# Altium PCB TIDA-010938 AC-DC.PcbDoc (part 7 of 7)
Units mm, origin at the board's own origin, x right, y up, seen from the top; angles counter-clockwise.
Board outline 275 x 170 mm, 4 copper layers (Top Layer, Layer 1, Layer 2, Bottom Layer), stack 1.787 mm thick; 711 components, 426 nets, 2196 pads, 1444 vias.
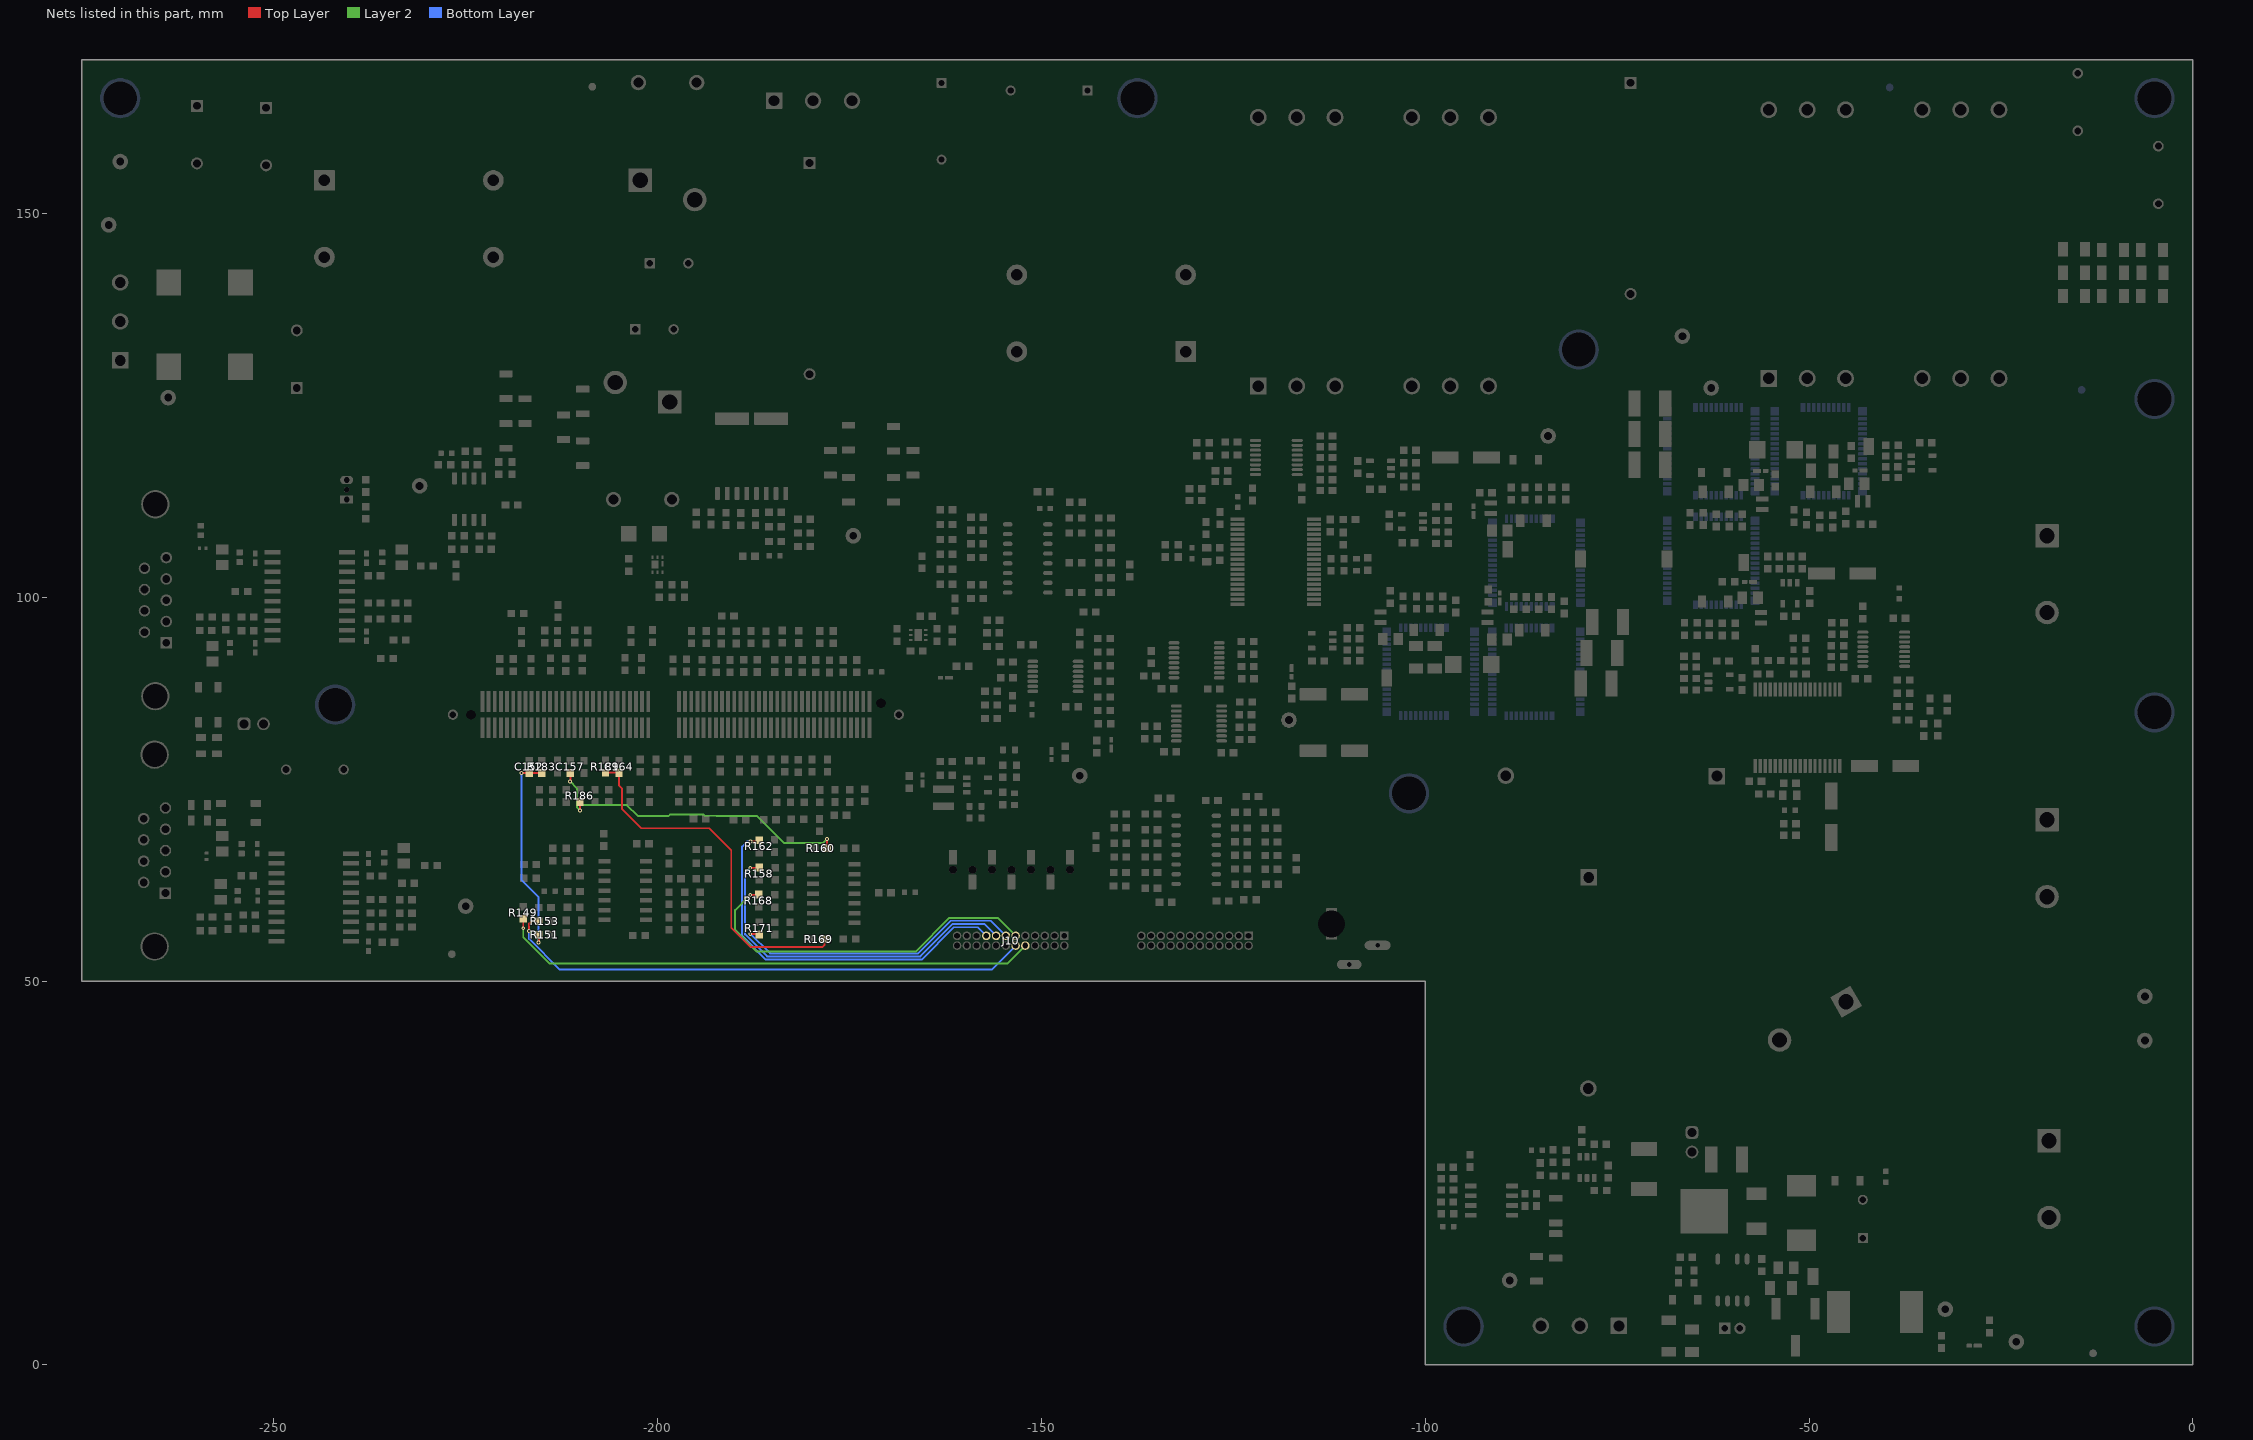
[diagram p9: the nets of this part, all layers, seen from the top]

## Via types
v1: diameter 0.508, hole 0.254, Top Layer to Bottom Layer, tented both sides, 1436 vias
v2: diameter 0.508, hole 0.254, Top Layer to Bottom Layer, 6 vias
v3: diameter 0.5, hole 0.2, Top Layer to Bottom Layer, 2 vias

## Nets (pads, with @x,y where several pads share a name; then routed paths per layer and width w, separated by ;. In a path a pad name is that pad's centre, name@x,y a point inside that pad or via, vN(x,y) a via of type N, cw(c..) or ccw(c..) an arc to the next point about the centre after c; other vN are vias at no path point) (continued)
VS_Batt1: C152.2 R151.2 R183.2 | length 26.6
  Top Layer w0.25: v1(-217.75,77.1) C152.2@-216.725,77.1 R183.2@-215.075,77.1 ; v1@-215.475,55.05 -215.473,55.052 R151.2@-215.473,56.02
  Bottom Layer w0.25: v1(-217.75,77.1) -217.75,63.177 -215.5,60.927 v1@-215.5,55.05
  other v1: -215.5,55
VS_Batt1+: J10.10 R149.2 | length 70.1
  Top Layer w0.25: R149.2@-217.5,58.094 -217.5,56.975 v1@-217.475,56.95
  Layer 2 w0.25: v1@-217.5,56.85 -217.494,56.844 -217.494,55.694 -214.1,52.3 -154.415,52.3 J10.10@-152.095,54.62
  other v1: -217.5,56.875
VS_Batt1-: J10.12 R153.2 | length 69.7
  Top Layer w0.25: v1(-216.725,56.5) -216.725,57.475 -216.402,57.798 R153.2@-215.473,57.798
  Bottom Layer w0.25: v1@-216.8,56.5 -216.725,56.425 -216.725,55.477 -212.748,51.5 -156.485,51.5 J10.12@-153.365,54.62
VS_Boost1: C157.2 R160.2 R186.1 | length 42.4
  Top Layer w0.25: v1@-211.363,76.137 C157.2@-211.363,77.101 ; v1(-210.119,72.194) R186.1@-210.119,73.328 ; R160.2@-177.975,67.475 -177.95,67.5 v1(-177.95,68.475)
  Layer 2 w0.25: v1(-211.4,76) -210.5,75.1 -210.5,72.922 ; v1(-210.119,72.194) -210.119,72.263 -210.5,72.645 -210.5,72.922 ; v1(-177.95,68.475) -178.425,68 -183.552,68 -187.052,71.5 -192.352,71.5 -192.381,71.529 -193.852,71.529 -194.002,71.679 -198.369,71.679 -198.548,71.5 -202.573,71.5 -203.996,72.922 -210.5,72.922
VS_Boost1+: J10.15 R158.2 | length 46.4
  Top Layer w0.25: v1(-187.925,64.75) -186.8,64.75 R158.2@-186.775,64.725
  Bottom Layer w0.25: v1@-187.95,64.725 -188.6,64.075 -188.6,56.077 -185.723,53.2 -165.775,53.2 -161.525,57.45 -157.465,57.45 J10.15@-155.905,55.89
VS_Boost1-: J10.17 R162.2 | length 49.5
  Top Layer w0.25: v1(-187.9,68.2) -186.7,68.2 R162.2@-186.675,68.225
  Bottom Layer w0.25: v1(-187.9,68.2) -188.297,68.2 -189,67.497 -189,55.911 -185.889,52.8 -165.609,52.8 -161.409,57 -158.285,57 J10.17@-157.175,55.89
VS_Boost2: C164.2 R169.2 R189.1 | length 47.2
  Top Layer w0.25: R189.1@-206.791,77.139 C164.2@-205.014,77.139 ; C164.2@-205.013,77.101 -205.013,75.436 -204.625,75.048 -204.625,72.375 -202.15,69.9 -193.275,69.9 -190.4,67.025 -190.4,56.95 -187.9,54.45 -178.5,54.45 -178.232,54.718 R169.2@-178.232,55.472
VS_Boost2+: J10.11 R168.2 | length 46.8
  Top Layer w0.25: v1(-187.925,61.225) R168.2@-186.825,61.225
  Layer 2 w0.25: v1@-188.05,61.1 -189.9,59.25 -189.9,56.65 -187.071,53.821 -166.379,53.821 -161.975,58.225 -155.7,58.225 J10.11@-153.365,55.89
VS_Boost2-: J10.13 R171.2 | length 38
  Top Layer w0.25: v1(-187.925,56.15) -186.95,56.15 R171.2@-186.925,56.125
  Bottom Layer w0.25: v1@-188,56.25 -185.35,53.6 -166.075,53.6 -161.825,57.85 -156.595,57.85 J10.13@-154.635,55.89
pads on no net: FID1.1 FID2.1 FID3.1 FID4.1 FID5.1 FID6.1 J2.2 J8. J8.6 J10.18 J10.19 J10.20 J10.21 J11.1 J11.2 J11.3 J11.4 J11.5 J11.6 J11.8 J11.9 J11.11 J11.15 J11.17 J11.20 J11.27 J11.32 J11.34 J11.36 J11.37 J11.41 J11.42 J11.43 J11.44 J11.45 J11.58 J11.60 J11.62 J11.64 J11.66 J11.71 J11.73 J11.85 J11.110 J11.113 J11.114 J11.115 J11.116 J11.117 J11.118 J11.119 J11.120 J11.181 J11.182 J11.185 J11.186 J12.18 J12.20 J12.22 J15.1 J15.8 J17.3 J17.4 J17.6 J17.7 J17.8 J17.9 L1.2 L1.3 L1.4 L1.5 L1.7 L1.8 L1.9 L1.10 L1.11 L1.12 L4.2 L4.3 L4.4 L4.5 L4.7 L4.8 L4.9 L4.10 L4.11 L4.12 LBL1.0 MP1. MP2. MP3. MP3.1 MP5. MP5.1 MP6. MP6.1 MP7. MP7.1 MP8. MP8.1 MP9. MP10. MP10.1 MP12. MP12.1 R6. R99.1 R125.2 R132.3 U2.1 U2.16 U2.17 U2.27 U2.43 U2.47 U2.52 U3.32 U4.1 U4.16 U4.17 U4.27 U4.43 U4.47 U4.52 U8.1 U8.16 U8.17 U8.27 U8.43 U8.47 U8.52 U9.1 U9.16 U9.17 U9.27 U9.43 U9.47 U9.52 U10.32 U11.1 U11.16 U11.17 U11.27 U11.43 U11.47 U11.52 U15.1 U15.16 U15.17 U15.27 U15.43 U15.47 U15.52 U16.10 U19.2 U19.5 U19.7@-166.06,94.626 U19.7@-166.06,95.526 U23.6 U24.6 U30.7

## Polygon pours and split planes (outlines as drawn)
"DC Bus-" on Bottom Layer "Bottom Layer-DC Bus- 1" (solid, remove dead copper, pour order 124): 59 vertices, not listed, extent -241.6,15 -26.5,123.5
SW_1 on Bottom Layer "BOTTOM_LAYER_SW_1_P025" (solid, remove dead copper, pour order 25): 31 vertices, not listed, extent -96.3,82.85 -82.75,130.125
12V_HVN on Bottom Layer "BOTTOM_LAYER_12V_HVN_P182" (solid, remove dead copper, pour order 182): -42,25 -42.25,25.25 -42.25,27.5 -42,27.75 -40,27.75 -39.5,27.25 -39.5,25
PE on Bottom Layer "BOTTOM_LAYER_PE_P154" (solid, remove dead copper, pour order 154): -272,137.25 -272,134.5 -259,134.5 -259,148 -265,154 -265,161 -264,162 -249,162 -249,167 -265,167 -267,169 -274,169 -274,156 -265,147 -265,137.25
NetF2_1 on Bottom Layer "BOTTOM_LAYER_NETF2_1_P150" (solid, remove dead copper, pour order 150): 22 vertices, not listed, extent -256,124 -241,159
VAC_N on Bottom Layer "BOTTOM_LAYER_VAC_N_P142" (solid, remove dead copper, pour order 142): -206,150 -204,148 -204,143 -202,141 -200,141 -199,142 -199,157 -201,159 -222,159 -224,157 -224,152 -222,150
PE2 on Bottom Layer "BOTTOM_LAYER_PE2_P140" (solid, remove dead copper, pour order 140): -143,161 -146.25,164.25 -146.25,166.75 -143.5,169.5 -143.353,169.353 -134.603,169.353 -131.5,166.25 -131.5,159.25 -141.25,159.25
ACLOAD_N on Bottom Layer "BOTTOM_LAYER_ACLOAD_N_P137" (solid, remove dead copper, pour order 137): 20 vertices, not listed, extent -198,138 -150,169
PE3 on Bottom Layer "BOTTOM_LAYER_PE3_P135" (solid, remove dead copper, pour order 135): -17,169 -17,167 -11,167 -11,163 -9,161 -6,161 -6,158 -3,158 -3,161 -1,161 -1,168.884 -0.934,168.95 -0.983,169
NetC103_2 on Bottom Layer "BOTTOM_LAYER_NETC103_2_P134" (solid, remove dead copper, pour order 134): 33 vertices, not listed, extent -135,125.25 -1,167
"DC Bus+" on Bottom Layer "BOTTOM_LAYER_DC_BUS+_P120" (solid, remove dead copper, pour order 120): -27,14 -27,54 -24,57 -24,111.75 -22,113.75 -11,113.75 -11,14
NetC229_1 on Bottom Layer "BOTTOM_LAYER_NETC229_1_P109" (solid, remove dead copper, pour order 109): -66.5,16 -67,16.5 -67,26 -65.5,27.5 -60.5,27.5 -60.5,16
"DC Bus+" on Bottom Layer "BOTTOM_LAYER_DC_BUS+_P096" (solid, remove dead copper, pour order 96): 19 vertices, not listed, extent -87.5,1.5 -69.5,39.5
"DC Bus-" on Bottom Layer "BOTTOM_LAYER_DC_BUS-_P086" (solid, remove dead copper, pour order 86): -102.75,83 -94.75,75 -94.75,69 -88.25,62.5 -80.75,62.5 -69,62.5 -60.75,70.75 -60.75,82.25 -62.5,84 -70.5,84 -82.5,72 -90.25,72 -92.5,74.25 -92.5,78.5 -97,83
"DC Bus-" on Bottom Layer "BOTTOM_LAYER_DC_BUS-_P082" (solid, remove dead copper, pour order 82): 19 vertices, not listed, extent -107,81.75 -96.75,95.25
SW_mid on Bottom Layer "BOTTOM_LAYER_SW_MID_P059" (solid, remove dead copper, pour order 59): 18 vertices, not listed, extent -81.25,100 -67,109.5
"DC Bus-" on Bottom Layer "Bottom Layer-DC Bus-" (solid, remove dead copper, pour order 72): 29 vertices, not listed, extent -79.5,109.5 -39.5,136
"DC Bus+" on Bottom Layer "BOTTOM_LAYER_DC_BUS+_P066" (solid, remove dead copper, pour order 66): -69,114.5 -69.95,115.45 -69.95,126.95 -69.4,127.5 -66,127.5 -66,126.5 -67,125.5 -67,122.5 -66.268,121.768 -66.268,116.732 -67.095,115.905 -67.095,114.5
"DC Bus+" on Bottom Layer "BOTTOM_LAYER_DC_BUS+_P007" (solid, remove dead copper, pour order 7): -82,95 -80.5,96.5 -78,96.5 -78,95 -78,79.75 -83.5,74.25 -89.35,74.25 -90.75,75.65 -90.75,78.05 -87.8,81 -83.75,81 -82,82.75
SW_2 on Bottom Layer "BOTTOM_LAYER_SW_2_P000" (solid, remove dead copper, pour order 0): 27 vertices, not listed, extent -65.25,97.4 -53,130
"DC Bus-" on Layer 1 "Layer 1-DC Bus-" (solid, remove dead copper, pour order 114): 47 vertices, not listed, extent -241.6,15 -75.5,123.5
GND_ISO_COMM on Layer 1 "LAYER_1_GND_ISO_COMM_P171" (solid, remove dead copper, pour order 171): -274.7,116.5 -272.4,118.8 -253.3,118.8 -248.6,114.1 -248.6,50.7 -273.3,50.7 -274.7,52.1
SW_2 on Layer 1 "LAYER_1_SW_2_P075" (solid, remove dead copper, pour order 75): 32 vertices, not listed, extent -67,87 -42,116.6
SW_1 on Layer 1 "Layer 1-SW_1" (solid, remove dead copper, pour order 57): 30 vertices, not listed, extent -117,93.5 -81.7,122
"DC Bus+" on Layer 1 "Layer 1-DC Bus+" (solid, remove dead copper, pour order 198): 63 vertices, not listed, extent -91.5,2 -2,130
VAC_SW+ on Layer 1 "LAYER_1_VAC_SW+_P194" (solid, remove dead copper, pour order 194): -182,127 -182,132 -179,135 -150,135 -148,133 -148,127
ACLOAD_N on Layer 1 "LAYER_1_ACLOAD_N_P193" (solid, remove dead copper, pour order 193): -151,140 -151,149 -165,149 -172,156 -182,156 -182,140
ACLOAD_N on Layer 1 "LAYER_1_ACLOAD_N_P192" (solid, remove dead copper, pour order 192): -197,150 -178,150 -172,156 -172,167 -176,167 -176,159 -177,158 -197,158 -197,149
PE on Layer 1 "LAYER_1_PE_P155" (solid, remove dead copper, pour order 155): -272,137.25 -272,134.5 -259,134.5 -259,148 -265,154 -265,161 -264,162 -249,162 -249,167 -265,167 -267,169 -274,169 -274,156 -265,147 -265,137.25
NetF2_1 on Layer 1 "LAYER_1_NETF2_1_P151" (solid, remove dead copper, pour order 151): 22 vertices, not listed, extent -256,124 -241,159
VAC_N on Layer 1 "LAYER_1_VAC_N_P145" (solid, remove dead copper, pour order 145): -224,152 -212,152 -210,150 -206,150 -204,148 -204,143 -202,141 -200,141 -199,142 -199,157 -201,159 -222,159 -224,157
VAC_L on Layer 1 "LAYER_1_VAC_L_P144" (solid, remove dead copper, pour order 144): -206.75,125.75 -210.25,129.25 -210.25,136 -215.25,141 -223,141 -225,143 -225,146 -223.5,147.5 -213.5,147.5 -202,136 -202,126.5 -202.75,125.75
NetC103_2 on Layer 1 "LAYER_1_NETC103_2_P132" (solid, remove dead copper, pour order 132): 31 vertices, not listed, extent -135,125.25 -1,167
NetC116_2 on Layer 1 "LAYER_1_NETC116_2_P106" (solid, remove dead copper, pour order 106): 24 vertices, not listed, extent -68.5,4 -44.5,20
"DC Bus-" on Layer 1 "LAYER_1_DC_BUS-_P092" (solid, remove dead copper, pour order 92): 23 vertices, not listed, extent -69.5,-1.25 -21.75,28.5
"DC Bus-" on Layer 1 "Layer 1-DC Bus- 1" (solid, remove dead copper, pour order 91): 34 vertices, not listed, extent -59,65.5 -28,121.5
"DC Bus-" on Top Layer "TOP_LAYER_DC_BUS-_P203" (solid, remove dead copper, pour order 203): 35 vertices, not listed, extent -242,16 -77.133,123
3V3_HVN on Top Layer "TOP_LAYER_3V3_HVN_P180" (solid, remove dead copper, pour order 180): 47 vertices, not listed, extent -125.525,50.5 -98.25,94
NetC103_1 on Top Layer "Top Layer-NetC103_1" (solid, remove dead copper, pour order 202): 30 vertices, not listed, extent -135,126.25 -10,169
"DC Bus-" on Top Layer "Top Layer-DC Bus-" (solid, remove dead copper, pour order 201): 63 vertices, not listed, extent -91.5,11.5 -2,127.038
SW_1 on Top Layer "TOP_LAYER_SW_1_P200" (solid, remove dead copper, pour order 200): -98,115 -99,116 -100,117 -100,121 -96,121 -95,120 -95,115
SW_2 on Top Layer "TOP_LAYER_SW_2_P199" (solid, remove dead copper, pour order 199): -45,105 -45,100 -41,100 -41,105
ACLOAD_N on Top Layer "TOP_LAYER_ACLOAD_N_P190" (solid, remove dead copper, pour order 190): -156,169 -151,169 -151,142 -153,140 -156,140
VAC_N on Top Layer "TOP_LAYER_VAC_N_P189" (solid, remove dead copper, pour order 189): -224,158 -224,152 -201,152 -200,153 -200,158
NetF2_1 on Top Layer "TOP_LAYER_NETF2_1_P188" (solid, remove dead copper, pour order 188): -253,158 -253,151 -241,151 -241,158
PE3 on Top Layer "TOP_LAYER_PE3_P187" (solid, remove dead copper, pour order 187): -17,168.75 -17,167 -11,167 -11,163 -9,161 -6,161 -6,158 -3,158 -3,161 -1,161 -0.983,161.017 -0.983,169 -16.75,169
PE2 on Top Layer "TOP_LAYER_PE2_P186" (solid, remove dead copper, pour order 186): -146.25,166.75 -143.647,169.353 -134.603,169.353 -131.5,166.25 -131.5,159.25 -141.25,159.25 -146.25,164.25
PE on Top Layer "TOP_LAYER_PE_P185" (solid, remove dead copper, pour order 185): -274,160 -265,160 -265,161 -264,162 -249,162 -249,167 -265,167 -267,169 -274,169
12V_HVN on Top Layer "TOP_LAYER_12V_HVN_P183" (solid, remove dead copper, pour order 183): -42.5,25.25 -39.25,25.25 -39.25,28 -42.5,28
SW_1 on Top Layer "TOP_LAYER_SW_1_P181" (solid, remove dead copper, pour order 181): -86.75,93.75 -84,93.75 -83.5,94.25 -83.5,96.5 -83.65,96.65 -84.9,96.65 -85.75,95.8 -86.75,95.8
SW_1 on Top Layer "TOP_LAYER_SW_1_P179" (solid, remove dead copper, pour order 179): -117.5,121.75 -117.5,120.295 -115.955,120.295 -115.25,121 -115.25,121.5 -115.5,121.75
12V_HVN on Top Layer "TOP_LAYER_12V_HVN_P178" (solid, remove dead copper, pour order 178): -111.25,89.75 -107.5,89.75 -107.5,79 -107.75,78.75 -111,78.75 -111.25,79
"DC Bus-" on Top Layer "TOP_LAYER_DC_BUS-_P177" (solid, remove dead copper, pour order 177): -125.5,109.5 -125.5,111.5 -123,111.5 -123,109.5
"DC Bus-" on Top Layer "TOP_LAYER_DC_BUS-_P176" (solid, remove dead copper, pour order 176): -123.5,98.5 -127.5,98.5 -127.5,102.5 -126.5,103.5 -126.5,105.05 -126.05,105.05 -126.05,105.625 -123.625,105.625 -123.5,105.5
SW_1 on Top Layer "TOP_LAYER_SW_1_P174" (solid, remove dead copper, pour order 174): -85.725,114.075 -85.75,114.1 -85.75,119 -84.5,119 -81.7,116.2 -81.7,114.075
"DC Bus-" on Top Layer "TOP_LAYER_DC_BUS-_P173" (solid, remove dead copper, pour order 173): -184.25,106.25 -184.25,111.5 -181.75,111.5 -181.446,111.196 -181.446,109.377 -181.76,109.064 -181.794,109.098 -182.446,109.098 -182.446,106.354 -182.55,106.25
"DC Bus-" on Top Layer "TOP_LAYER_DC_BUS-_P172" (solid, remove dead copper, pour order 172): -117,78.75 -116.5,78.25 -113,78.25 -112.25,79 -112.25,89.25 -112.5,89.5 -115.75,89.5 -116.5,88.75 -116.5,85.75 -116.75,85.5 -118.25,85.5 -119,84.75 -119,78.75
"DC Bus-" on Top Layer "TOP_LAYER_DC_BUS-_P170" (solid, remove dead copper, pour order 170): -107,85.75 -103,85.75 -103,93.55 -107,93.55
"DC Bus-" on Top Layer "TOP_LAYER_DC_BUS-_P169" (solid, remove dead copper, pour order 169): -43.399,118.351 -41.25,118.351 -41.25,120.849 -43.397,120.849 -43.399,120.851
SW_mid on Top Layer "TOP_LAYER_SW_MID_P168" (solid, remove dead copper, pour order 168): -69.5,103.75 -67,103.75 -67,106.25 -67.002,106.248 -69.498,106.248 -69.5,106.25
SW_mid on Top Layer "TOP_LAYER_SW_MID_P166" (solid, remove dead copper, pour order 166): -81.25,103.25 -78.75,103.25 -78.75,106.75 -81.25,106.75
NetR112_2 on Top Layer "TOP_LAYER_NETR112_2_P165" (solid, remove dead copper, pour order 165): -213.5,121.4 -213.5,119.65 -208.25,119.65 -208.25,121.4
NetR111_2 on Top Layer "TOP_LAYER_NETR111_2_P164" (solid, remove dead copper, pour order 164): -213.5,124.65 -213.5,122.9 -208.25,122.9 -208.25,124.65
NetR123_2 on Top Layer "TOP_LAYER_NETR123_2_P163" (solid, remove dead copper, pour order 163): -221,123.65 -221,121.9 -215.75,121.9 -215.75,123.65
NetR122_2 on Top Layer "TOP_LAYER_NETR122_2_P162" (solid, remove dead copper, pour order 162): -221,126.9 -221,125.15 -215.75,125.15 -215.75,126.9
NetC81_1 on Top Layer "TOP_LAYER_NETC81_1_P161" (solid, remove dead copper, pour order 161): -172.25,113.269 -172.25,111 -168.167,111 -168.167,113.269
NetC45_1 on Top Layer "TOP_LAYER_NETC45_1_P160" (solid, remove dead copper, pour order 160): -178.25,113.275 -178.25,111 -174,111 -174,113.275
NetR128_2 on Top Layer "TOP_LAYER_NETR128_2_P159" (solid, remove dead copper, pour order 159): -171.025,116.75 -171.025,115 -165.775,115 -165.775,116.75
NetR117_2 on Top Layer "TOP_LAYER_NETR117_2_P158" (solid, remove dead copper, pour order 158): -179.25,116.55 -179.25,114.8 -174,114.8 -174,116.55
NetR127_2 on Top Layer "TOP_LAYER_NETR127_2_P157" (solid, remove dead copper, pour order 157): -170.75,120 -170.75,118.5 -163.5,118.5 -163.5,120
NetR116_2 on Top Layer "TOP_LAYER_NETR116_2_P156" (solid, remove dead copper, pour order 156): -179.25,120.25 -179.25,118.5 -174,118.5 -174,120.25
AC_L on Top Layer "TOP_LAYER_AC_L_P148" (solid, remove dead copper, pour order 148): -273,140 -265,140 -265,138 -262,138 -262,146 -273,146
NetF1_1 on Top Layer "TOP_LAYER_NETF1_1_P149" (solid, remove dead copper, pour order 149): -256,146 -261,151 -263,153 -263,158 -257,158 -257,151 -255,149 -241,149 -241,134 -250,134 -250,137 -254,137 -256,139
AC_N on Top Layer "TOP_LAYER_AC_N_P147" (solid, remove dead copper, pour order 147): -273,132 -262,132 -262,125 -263,124 -273,124
NetF2_1 on Top Layer "TOP_LAYER_NETF2_1_P146" (solid, remove dead copper, pour order 146): -256,131.65 -250.65,131.65 -248,129 -245,129 -244,128 -244,125 -245,124 -252,124 -256,128
VAC_L on Top Layer "TOP_LAYER_VAC_L_P141" (solid, remove dead copper, pour order 141): -206.75,125.75 -210.25,129.25 -210.25,136 -215.25,141 -223,141 -225,143 -225,146 -223.5,147.5 -213.5,147.5 -202,136 -202,126.5 -202.75,125.75
ACLOAD_L on Top Layer "TOP_LAYER_ACLOAD_L_P138" (solid, remove dead copper, pour order 138): 28 vertices, not listed, extent -200.5,122.5 -183.25,167.25
VAC_SW+ on Top Layer "TOP_LAYER_VAC_SW+_P136" (solid, remove dead copper, pour order 136): 19 vertices, not listed, extent -187.5,122.75 -150,169
NetC103_2 on Top Layer "TOP_LAYER_NETC103_2_P127" (solid, remove dead copper, pour order 127): -4.34,148.34 -7,151 -7,152 -1.34,152 -1.34,137 -4.34,137
NetR77_1 on Top Layer "TOP_LAYER_NETR77_1_P126" (solid, remove dead copper, pour order 126): -9.42,137 -6.42,137 -6.42,147 -9.42,147
NetR185_1 on Top Layer "TOP_LAYER_NETR185_1_P125" (solid, remove dead copper, pour order 125): -14.5,137 -11.5,137 -11.5,147 -14.5,147
"DC Bus+" on Top Layer "TOP_LAYER_DC_BUS+_P117" (solid, remove dead copper, pour order 117): -87,11.5 -87,4 -87,1.5 -82,1.5 -82,10.5 -83,11.5
NetR23_2 on Top Layer "TOP_LAYER_NETR23_2_P116" (solid, remove dead copper, pour order 116): -85,17 -85,18.5 -84.5,19 -80.5,19 -80,18.5 -80,17 -80.5,16.5 -84.5,16.5
NetR21_2 on Top Layer "TOP_LAYER_NETR21_2_P115" (solid, remove dead copper, pour order 115): -87,13 -87,15 -81,15 -81,13
NetQ2_3 on Top Layer "TOP_LAYER_NETQ2_3_P110" (solid, remove dead copper, pour order 110): -56.5,9 -54,9 -54,11 -53.5,11.5 -53.5,13.5 -53.516,13.516 -54.909,13.516 -55.425,13 -56.625,13 -57,12.625 -57,9.5
NetC118_1 on Top Layer "TOP_LAYER_NETC118_1_P104" (solid, remove dead copper, pour order 104): -39,4.5 -38,3.5 -30,3.5 -29,4.5 -29,9 -37.5,17.5 -44.5,17.5 -45.5,16.5 -45.5,15.5 -39,9
NetC116_2 on Top Layer "TOP_LAYER_NETC116_2_P103" (solid, remove dead copper, pour order 103): -52,5.5 -48.75,5.5 -48.75,4 -44.5,4 -44.5,13 -49.5,18 -53.5,18 -54,17.5 -54,15.5 -52.5,14 -52.5,11.5 -53,11 -53,8 -52,7
NetC229_1 on Top Layer "TOP_LAYER_NETC229_1_P101" (solid, remove dead copper, pour order 101): -67,17 -67,27.75 -66.3,28.45 -60.5,28.45 -60.5,17
NetJ2_1 on Top Layer "TOP_LAYER_NETJ2_1_P100" (solid, remove dead copper, pour order 100): -69.5,16.25 -72,13.75 -72,1.5 -77.5,1.5 -77.5,16 -73.5,20 -73.5,23.5 -69.5,23.5 -73.5,23.5 -69.5,23.5
"DC Bus-" on Top Layer "TOP_LAYER_DC_BUS-_P089" (solid, remove dead copper, pour order 89): -52.5,79 -41,79 -40.5,78.5 -40.5,74 -42.75,71.75 -49.5,71.75 -51.25,73.5 -52.5,73.5
"DC Bus+" on Top Layer "Top Layer-DC Bus+" (solid, remove dead copper, pour order 85): 21 vertices, not listed, extent -92.5,72.75 -77.25,98.5
SW_1 on Top Layer "TOP_LAYER_SW_1_P076" (solid, remove dead copper, pour order 76): 17 vertices, not listed, extent -90,105.25 -83.25,110.979
SW_2 on Top Layer "TOP_LAYER_SW_2_P074" (solid, remove dead copper, pour order 74): -61.5,100.5 -58.325,100.5 -58.325,100.9 -60.15,100.9 -60.75,101.5 -60.75,102.5 -61,102.75 -63.25,102.75 -66,100 -66,98.5 -63.343,98.5 -63.343,99.157 -62.75,99.75 -62.25,99.75
"DC Bus-" on Top Layer "TOP_LAYER_DC_BUS-_P073" (solid, remove dead copper, pour order 73): -51.5,113 -51.5,115 -51.25,115.25 -46.75,115.25 -48.82,113.18 -48.82,113
"DC Bus+" on Top Layer "TOP_LAYER_DC_BUS+_P063" (solid, remove dead copper, pour order 63): -69.95,115.45 -69,114.5 -67.095,114.5 -67.095,115.905 -66,117 -66,127.5 -69.4,127.5 -69.95,126.95
SW_1 on Top Layer "TOP_LAYER_SW_1_P056" (solid, remove dead copper, pour order 56): -115.25,98.75 -116,99.5 -116,104 -107.075,104 -107.075,102.948 -109.023,101 -111.273,98.75
SW_2 on Top Layer "TOP_LAYER_SW_2_P053" (solid, remove dead copper, pour order 53): -65.8,87.2 -67.014,87.2 -67.024,87.209 -67,87.233 -67,95.5 -62.75,95.5 -62.4,95.15 -62.4,94.1 -65,94.1 -65.8,93.3
SW_2 on Top Layer "TOP_LAYER_SW_2_P052" (solid, remove dead copper, pour order 52): -54,87.1 -54,89.4 -54.2,89.6 -54.2,90.5 -53.9,90.8 -53.2,90.8 -52.8,90.4 -52.8,89 -52.9,88.9 -52.9,87.1
SW_2 on Top Layer "TOP_LAYER_SW_2_P051" (solid, remove dead copper, pour order 51): -51,87 -51.5,87.5 -51.5,89 -51,89 -51,95 -50,95 -49.65,94.65 -49.65,92.15 -49.2,91.7 -47.454,89.954 -46.3,89.954 -44.846,88.5 -44,88.5 -44,87
"DC Bus-" on Top Layer "TOP_LAYER_DC_BUS-_P048" (solid, remove dead copper, pour order 48): -41.8,110.6 -41.8,111.8 -40.7,112.9 -40.7,120.4 -40.5,120.6 -39.5,120.6 -39.3,120.4 -39.3,111.7 -40.4,110.6
"DC Bus-" on Top Layer "TOP_LAYER_DC_BUS-_P047" (solid, remove dead copper, pour order 47): 21 vertices, not listed, extent -45.5,110.2 -40.4,115.8
SN_Relays_PreCharge on Top Layer "TOP_LAYER_SN_RELAYS_PRECHARGE_P043" (solid, remove dead copper, pour order 43): -199.425,114.1 -197.402,114.102 -196.375,113.075 -196.375,108.45 -198.625,106.2 -199.5,106.2 -199.775,105.925 -199.775,102.725 -199.975,102.525 -201.025,102.525 -201.35,102.85 -201.35,112.225 -199.475,114.1
"DC Bus-" on Layer 2 "Layer 2-DC Bus- 1" (solid, remove dead copper, pour order 196): 84 vertices, not listed, extent -241.5,0.75 -21.666,123.5
GND_ISO_COMM on Layer 2 "LAYER_2_GND_ISO_COMM_P045" (solid, remove dead copper, pour order 45): -274.7,116.5 -272.4,118.8 -253.3,118.8 -248.6,114.1 -248.6,50.7 -273.3,50.7 -274.7,52.1
SW_2 on Layer 2 "LAYER_2_SW_2_P050" (solid, remove dead copper, pour order 50): 29 vertices, not listed, extent -67,87 -42,116.6
SW_1 on Layer 2 "Layer 2-SW_1" (solid, remove dead copper, pour order 55): 29 vertices, not listed, extent -117,93.5 -81.7,122
NetC103_1 on Layer 2 "LAYER_2_NETC103_1_P133" (solid, remove dead copper, pour order 133): 30 vertices, not listed, extent -134.8,126.25 -9.8,169
VAC_SW+ on Layer 2 "LAYER_2_VAC_SW+_P195" (solid, remove dead copper, pour order 195): -181,126 -181,134 -151,134 -151,126
PE on Layer 2 "LAYER_2_PE_P153" (solid, remove dead copper, pour order 153): -272,137.25 -272,134.5 -259,134.5 -259,148 -265,154 -265,161 -264,162 -249,162 -249,167 -265,167 -267,169 -274,169 -274,156 -265,147 -265,137.25
NetF2_1 on Layer 2 "LAYER_2_NETF2_1_P152" (solid, remove dead copper, pour order 152): 22 vertices, not listed, extent -256,124 -241,159
PE2 on Layer 2 "LAYER_2_PE2_P139" (solid, remove dead copper, pour order 139): 17 vertices, not listed, extent -181.25,154.5 -131.5,169.5
"DC Bus-" on Layer 2 "LAYER_2_DC_BUS-_P119" (solid, remove dead copper, pour order 119): -21.5,112 -11,112 -11,14 -21.5,14 -21.5,56
"DC Bus+" on Layer 2 "LAYER_2_DC_BUS+_P097" (solid, remove dead copper, pour order 97): 19 vertices, not listed, extent -87.5,1.5 -69.5,38.5
"DC Bus-" on Layer 2 "LAYER_2_DC_BUS-_P077" (solid, remove dead copper, pour order 77): 21 vertices, not listed, extent -107,62.5 -60.5,99
"DC Bus-" on Layer 2 "Layer 2-DC Bus-" (solid, remove dead copper, pour order 69): 21 vertices, not listed, extent -75,113 -39.5,136.5

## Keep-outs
Keep-Out Layer:
  text ".Layer_Name" at -276.017,-104.177 h0.5

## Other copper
Top Layer:
  pour cut-out: -82.75,36 ccw(c-78.75,36) -78.75,32 ccw(c-78.75,36) -74.75,36 ccw(c-78.75,36) -78.75,40 ccw(c-78.75,36)
  pour cut-out: -57.845,42.311 ccw(c-53.845,42.311) -53.845,38.311 ccw(c-53.845,42.311) -49.845,42.311 ccw(c-53.845,42.311) -53.845,46.311 ccw(c-53.845,42.311)
  pour cut-out: -22.75,19.2 ccw(c-18.75,19.2) -18.75,15.2 ccw(c-18.75,19.2) -14.75,19.2 ccw(c-18.75,19.2) -18.75,23.2 ccw(c-18.75,19.2)
  pour cut-out: -23,61 ccw(c-19,61) -19,57 ccw(c-19,61) -15,61 ccw(c-19,61) -19,65 ccw(c-19,61)
  pour cut-out: -23,98 ccw(c-19,98) -19,94 ccw(c-19,98) -15,98 ccw(c-19,98) -19,102 ccw(c-19,98)
  pour cut-out: -249.4,86.1 ccw(c-242.1,86.1) -242.1,78.8 ccw(c-242.1,86.1) -234.8,86.1 ccw(c-242.1,86.1) -242.1,93.4 ccw(c-242.1,86.1)
  pour cut-out: -249.4,86.1 ccw(c-242.1,86.1) -242.1,78.8 ccw(c-242.1,86.1) -234.8,86.1 ccw(c-242.1,86.1) -242.1,93.4 ccw(c-242.1,86.1)
  pour cut-out: -12.4,5.1 ccw(c-5.1,5.1) -5.1,-2.2 ccw(c-5.1,5.1) 2.2,5.1 ccw(c-5.1,5.1) -5.1,12.4 ccw(c-5.1,5.1)
  pour cut-out: -12.4,85.1 ccw(c-5.1,85.1) -5.1,77.8 ccw(c-5.1,85.1) 2.2,85.1 ccw(c-5.1,85.1) -5.1,92.4 ccw(c-5.1,85.1)
  pour cut-out: -79.75,61.5 -78.25,61.5 -78.25,45 -79.75,45
  text ".Layer_Name" at -276.017,-104.177 h0.5
Layer 1:
  pour cut-out: -82.7,63.5 ccw(c-78.7,63.5) -78.7,59.5 ccw(c-78.7,63.5) -74.7,63.5 ccw(c-78.7,63.5) -78.7,67.5 ccw(c-78.7,63.5)
  pour cut-out: -22.75,29.2 ccw(c-18.75,29.2) -18.75,25.2 ccw(c-18.75,29.2) -14.75,29.2 ccw(c-18.75,29.2) -18.75,33.2 ccw(c-18.75,29.2)
  pour cut-out: -49.184,47.311 ccw(c-45.184,47.311) -45.184,43.311 ccw(c-45.184,47.311) -41.184,47.311 ccw(c-45.184,47.311) -45.184,51.311 ccw(c-45.184,47.311)
  pour cut-out: -23,71 ccw(c-19,71) -19,67 ccw(c-19,71) -15,71 ccw(c-19,71) -19,75 ccw(c-19,71)
  pour cut-out: -23,108 ccw(c-19,108) -19,104 ccw(c-19,108) -15,108 ccw(c-19,108) -19,112 ccw(c-19,108)
  pour cut-out: -249.4,86.1 ccw(c-242.1,86.1) -242.1,78.8 ccw(c-242.1,86.1) -234.8,86.1 ccw(c-242.1,86.1) -242.1,93.4 ccw(c-242.1,86.1)
  pour cut-out: -80.25,61.5 -77.75,61.5 -77.75,44.737 -80.25,44.737
Layer 2:
  pour cut-out: -65.586,127.261 ccw(c-62.735,127.261) -62.735,124.411 ccw(c-62.735,127.261) -59.885,127.261 ccw(c-62.735,127.261) -62.735,130.112 ccw(c-62.735,127.261)
  pour cut-out: -58.086,128.511 ccw(c-55.235,128.511) -55.235,125.661 ccw(c-55.235,128.511) -52.385,128.511 ccw(c-55.235,128.511) -55.235,131.362 ccw(c-55.235,128.511)
  pour cut-out: -93.5,76.75 ccw(c-89.5,76.75) -89.5,72.75 ccw(c-89.5,76.75) -85.5,76.75 ccw(c-89.5,76.75) -89.5,80.75 ccw(c-89.5,76.75)
  pour cut-out: -22.75,19.2 ccw(c-18.75,19.2) -18.75,15.2 ccw(c-18.75,19.2) -14.75,19.2 ccw(c-18.75,19.2) -18.75,23.2 ccw(c-18.75,19.2)
  pour cut-out: -23,61 ccw(c-19,61) -19,57 ccw(c-19,61) -15,61 ccw(c-19,61) -19,65 ccw(c-19,61)
  pour cut-out: -23,98 ccw(c-19,98) -19,94 ccw(c-19,98) -15,98 ccw(c-19,98) -19,102 ccw(c-19,98)
  pour cut-out: -249.4,86.1 ccw(c-242.1,86.1) -242.1,78.8 ccw(c-242.1,86.1) -234.8,86.1 ccw(c-242.1,86.1) -242.1,93.4 ccw(c-242.1,86.1)
  pour cut-out: -54.5,45.5 -50.5,45.5 -45.5,50.5 -41,50.5 -41,41.5 -46.625,35.875 -46.625,32 -51,32 -57.5,38.5 -57.5,42.5
Bottom Layer:
  pour cut-out: -91.304,98.054 ccw(c-90.804,98.054) -90.804,97.554 ccw(c-90.804,98.054) -90.304,98.054 ccw(c-90.804,98.054) -90.804,98.554 ccw(c-90.804,98.054)
  pour cut-out: -96.466,111.566 ccw(c-95.966,111.566) -95.966,111.066 ccw(c-95.966,111.566) -95.466,111.566 ccw(c-95.966,111.566) -95.966,112.066 ccw(c-95.966,111.566)
  pour cut-out: -96.504,119.954 ccw(c-96.004,119.954) -96.004,119.454 ccw(c-96.004,119.954) -95.504,119.954 ccw(c-96.004,119.954) -96.004,120.454 ccw(c-96.004,119.954)
  pour cut-out: -96.504,115.954 ccw(c-96.004,115.954) -96.004,115.454 ccw(c-96.004,115.954) -95.504,115.954 ccw(c-96.004,115.954) -96.004,116.454 ccw(c-96.004,115.954)
  pour cut-out: -90.55,114.005 ccw(c-90.05,114.005) -90.05,113.505 ccw(c-90.05,114.005) -89.55,114.005 ccw(c-90.05,114.005) -90.05,114.505 ccw(c-90.05,114.005)
  pour cut-out: -90.55,113.005 ccw(c-90.05,113.005) -90.05,112.505 ccw(c-90.05,113.005) -89.55,113.005 ccw(c-90.05,113.005) -90.05,113.505 ccw(c-90.05,113.005)
  pour cut-out: -84.55,117.005 ccw(c-84.05,117.005) -84.05,116.505 ccw(c-84.05,117.005) -83.55,117.005 ccw(c-84.05,117.005) -84.05,117.505 ccw(c-84.05,117.005)
  pour cut-out: -83.55,117.005 ccw(c-83.05,117.005) -83.05,116.505 ccw(c-83.05,117.005) -82.55,117.005 ccw(c-83.05,117.005) -83.05,117.505 ccw(c-83.05,117.005)
  pour cut-out: -83.55,116.005 ccw(c-83.05,116.005) -83.05,115.505 ccw(c-83.05,116.005) -82.55,116.005 ccw(c-83.05,116.005) -83.05,116.505 ccw(c-83.05,116.005)
  pour cut-out: -84.054,115.604 ccw(c-83.554,115.604) -83.554,115.104 ccw(c-83.554,115.604) -83.054,115.604 ccw(c-83.554,115.604) -83.554,116.104 ccw(c-83.554,115.604)
  pour cut-out: -84.55,116.005 ccw(c-84.05,116.005) -84.05,115.505 ccw(c-84.05,116.005) -83.55,116.005 ccw(c-84.05,116.005) -84.05,116.505 ccw(c-84.05,116.005)
  pour cut-out: -55.004,112.454 ccw(c-54.504,112.454) -54.504,111.954 ccw(c-54.504,112.454) -54.004,112.454 ccw(c-54.504,112.454) -54.504,112.954 ccw(c-54.504,112.454)
  pour cut-out: -88.954,101.379 ccw(c-88.454,101.379) -88.454,100.879 ccw(c-88.454,101.379) -87.954,101.379 ccw(c-88.454,101.379) -88.454,101.879 ccw(c-88.454,101.379)
  pour cut-out: -85.704,101.354 ccw(c-85.204,101.354) -85.204,100.854 ccw(c-85.204,101.354) -84.704,101.354 ccw(c-85.204,101.354) -85.204,101.854 ccw(c-85.204,101.354)
  pour cut-out: -22.75,29.2 ccw(c-18.75,29.2) -18.75,25.2 ccw(c-18.75,29.2) -14.75,29.2 ccw(c-18.75,29.2) -18.75,33.2 ccw(c-18.75,29.2)
  pour cut-out: -23,71 ccw(c-19,71) -19,67 ccw(c-19,71) -15,71 ccw(c-19,71) -19,75 ccw(c-19,71)
  pour cut-out: -23,108 ccw(c-19,108) -19,104 ccw(c-19,108) -15,108 ccw(c-19,108) -19,112 ccw(c-19,108)
  pour cut-out: -249.5,86.55 ccw(c-242.2,86.55) -242.2,79.25 ccw(c-242.2,86.55) -234.9,86.55 ccw(c-242.2,86.55) -242.2,93.85 ccw(c-242.2,86.55)
  pour cut-out: -87.3,132.25 ccw(c-80,132.25) -80,124.95 ccw(c-80,132.25) -72.7,132.25 ccw(c-80,132.25) -80,139.55 ccw(c-80,132.25)
  pour cut-out: -12.35,85.05 ccw(c-5.05,85.05) -5.05,77.75 ccw(c-5.05,85.05) 2.25,85.05 ccw(c-5.05,85.05) -5.05,92.35 ccw(c-5.05,85.05)
  pour cut-out: -102.35,5.05 ccw(c-95.05,5.05) -95.05,-2.25 ccw(c-95.05,5.05) -87.75,5.05 ccw(c-95.05,5.05) -95.05,12.35 ccw(c-95.05,5.05)
  pour cut-out: -109.45,74.5 ccw(c-102.15,74.5) -102.15,67.2 ccw(c-102.15,74.5) -94.85,74.5 ccw(c-102.15,74.5) -102.15,81.8 ccw(c-102.15,74.5)
  pour cut-out: -59.504,116.254 ccw(c-59.004,116.254) -59.004,115.754 ccw(c-59.004,116.254) -58.504,116.254 ccw(c-59.004,116.254) -59.004,116.754 ccw(c-59.004,116.254)
  pour cut-out: -59.204,108.404 ccw(c-58.704,108.404) -58.704,107.904 ccw(c-58.704,108.404) -58.204,108.404 ccw(c-58.704,108.404) -58.704,108.904 ccw(c-58.704,108.404)
  pour cut-out: -62.596,108.404 ccw(c-62.096,108.404) -62.096,107.904 ccw(c-62.096,108.404) -61.596,108.404 ccw(c-62.096,108.404) -62.096,108.904 ccw(c-62.096,108.404)
  pour cut-out: -58,41.5 -54.5,38 -46.5,38 -41.5,43 -41.5,54.602 -50.602,45.5 -57,45.5 -58,44.5
  text ".Layer_Name" at -276.017,-104.177 h0.5

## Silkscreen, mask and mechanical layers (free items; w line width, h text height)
Top Overlay:
  drawing of 204 lines, arcs and shapes, not listed
  text "L1" at -268.8,145.9 h2.1 r90
  text "PE" at -262.8,134.7 h0.7 r90
  text "N" at -268.5,125.4 h2.1 r90
  text ".PRJ_Number" at -211.728,50.824 h3.05
  text "VER: .PCB_Rev" at -184.652,50.789 h3.05
  text "DC-" at -73.25,9.523 h2.1
  text "DC+" at -83.775,9.498 h2.1
  text ".Layer_Name" at -276.017,-104.177 h0.5
Bottom Overlay:
  text ".Layer_Name" at -276.017,-104.177 h0.5
Top Paste:
  text ".Layer_Name" at -276.017,-104.177 h0.5
Bottom Paste:
  text ".Layer_Name" at -276.017,-104.177 h0.5
Top Solder:
  region: -8.504,164.92 ccw(c-5.004,164.92) -5.004,161.42 ccw(c-5.004,164.92) -1.504,164.92 ccw(c-5.004,164.92) -5.004,168.42 ccw(c-5.004,164.92)
  region: -141.004,164.92 ccw(c-137.504,164.92) -137.504,161.42 ccw(c-137.504,164.92) -134.004,164.92 ccw(c-137.504,164.92) -137.504,168.42 ccw(c-137.504,164.92)
  region: -273.504,164.92 ccw(c-270.004,164.92) -270.004,161.42 ccw(c-270.004,164.92) -266.504,164.92 ccw(c-270.004,164.92) -270.004,168.42 ccw(c-270.004,164.92)
  text ".Layer_Name" at -276.017,-104.177 h0.5
  text ".Layer_Name" at -276.017,-104.177 h0.5
Bottom Solder:
  text ".Layer_Name" at -276.017,-104.177 h0.5
Drill Guide:
  text ".Layer_Name" at -276.017,-104.177 h0.5
M1 Board Outline:
  lines w0.5: -275,50 -100,50 -100,0 0,0 0,170 -275,170 -275,50 ; -255,107.75 -255,120.75 -242.5,120.75 -242.5,107.75 -255,107.75
  text ".Layer_Name" at -276.017,-104.177 h0.5
M2 Board Dimensions:
  rectangle: -290.673,-89.356 -287.498,-86.181
  rectangle: -287.498,-92.531 -277.973,-89.356
  lines w0.178: -290.673,-89.356 -265.273,-89.356 ; -287.498,-92.531 -287.498,-86.181 ; -284.323,-92.531 -284.323,-86.181 ; -277.973,-92.531 -277.973,-86.181 ; -271.623,-92.531 -271.623,-86.181 ; -290.673,-92.531 -290.673,-86.181 -265.273,-86.181 -265.273,-92.531 -290.673,-92.531
  text ".Layer_Name" at -276.017,-104.177 h0.5
M3 3D STEP Top:
  text ".Layer_Name" at -276.017,-104.177 h0.5
M4 3D STEP Bottom:
  text ".Layer_Name" at -276.017,-104.177 h0.5
M5 Assembly Top:
  lines w0.254: -298.09,-105.997 -130.45,-105.997 ; -298.09,-100.832 -130.399,-100.832 ; -298.09,-95.668 -298.09,-111.162 -196.363,-111.162 -130.399,-111.162 -130.399,-95.668 -298.077,-95.668 -298.077,-111.162 -258.059,-111.162 ; -235.479,-111.162 -235.479,-95.668 ; -203.297,-100.832 -203.297,-95.668 ; -181.961,-100.832 -181.961,-95.668 ; -166.162,-111.327 -166.162,-106.175
  text "COMPONENTS MARKED 'DNP' SHOULD NOT BE POPULATED." at -261.374,-90.461 h0.5
  text "ASSEMBLY VARIANT:" at -261.387,-93.394 h0.5
  text ".VariantName" at -235.072,-93.394 h0.5
  text "PCB VIEWED FROM TOP SIDE" at -296.477,-99.025 h0.5
  text "BOARD #:" at -233.574,-99.025 h0.5
  text ".PRJ_Number" at -219.718,-99.025 h0.5
  text "REV:" at -198.268,-99.025 h0.5
  text ".PCB_Rev" at -190.864,-99.025 h0.5
  text "SVN REV:" at -176.983,-99.025 h0.5
  text ".VersionControl_RevNumber" at -164.13,-99.025 h0.5
  text "TID #:" at -233.574,-104.189 h0.5
  text ".TID" at -219.718,-104.189 h0.5
  text "PLOT NAME =" at -296.477,-109.405 h0.5
  text ".plot_File_Name" at -276.017,-109.405 h0.5
  text "GENERATED    :" at -233.523,-109.405 h0.5
  text ".Print_Date" at -211.438,-109.405 h0.5
  text ".Print_Time" at -192.921,-109.405 h0.5
  text "TEXAS INSTRUMENTS" at -160.803,-109.405 h0.5
M6 Assembly Bottom:
  lines w0.254: -298.102,-100.845 -130.412,-100.845 ; -298.052,-106.01 -130.412,-106.01 ; -262.339,-111.34 -262.339,-106.188 ; -246.54,-100.845 -246.54,-95.68 ; -225.204,-100.845 -225.204,-95.68 ; -193.023,-111.174 -193.023,-95.68 ; -170.442,-111.174 -130.424,-111.174 -130.424,-95.68 -298.102,-95.68 -298.102,-111.174 -232.139,-111.174 -130.412,-111.174 -130.412,-95.68
  text "COMPONENTS MARKED 'DNP' SHOULD NOT BE POPULATED." at -135.682,-90.448 h0.5
  text ".VariantName" at -162.2,-93.394 h0.5
  text "ASSEMBLY VARIANT:" at -135.809,-93.394 h0.5
  text ".VersionControl_RevNumber" at -264.371,-99.038 h0.5
  text "SVN REV:" at -251.519,-99.038 h0.5
  text ".PCB_Rev" at -237.638,-99.038 h0.5
  text "REV:" at -230.234,-99.038 h0.5
  text ".PRJ_Number" at -208.783,-99.038 h0.5
  text "BOARD #:" at -194.928,-99.038 h0.5
  text "PCB VIEWED FROM BOTTOM SIDE" at -132.025,-99.038 h0.5
  text ".TID" at -208.783,-104.202 h0.5
  text "TID #:" at -194.928,-104.202 h0.5
  text "TEXAS INSTRUMENTS" at -267.699,-109.418 h0.5
  text ".Print_Time" at -235.58,-109.418 h0.5
  text ".Print_Date" at -217.064,-109.418 h0.5
  text "GENERATED    :" at -194.978,-109.418 h0.5
  text ".plot_File_Name" at -152.484,-109.418 h0.5
  text "PLOT NAME =" at -132.025,-109.418 h0.5
M9 Title Sheet:
  drawing of 56 lines, arcs and shapes, not listed
  text "1" at -263.118,235.735 h1.78
  text "2" at -178.646,235.735 h1.78
  text "3" at -94.064,235.735 h1.78
  text "4" at -9.355,235.735 h1.78
  text "5" at 75.1,235.735 h1.78
  text "6" at 159.809,235.735 h1.78
  text "A" at -301.76,190.574 h1.78
  text "A" at 198.62,190.574 h1.78
  text "B" at -301.76,95.324 h1.78
  text "B" at 198.62,95.324 h1.78
  text "C" at -301.76,0.074 h1.78
  text "C" at 198.62,0.074 h1.78
  text "D" at -301.76,-95.176 h1.78
  text "D" at 198.62,-95.176 h1.78
  text "PROJECT TITLE:" at 120.032,-97.335 h1.14
  text ".PRJ_Title" at 121.302,-100.721 h1.78
  text "DESIGNED FOR:" at 120.032,-104.98 h1.14
  text ".PRJ_Customer" at 121.302,-108.536 h1.78
  text "FILE NAME:" at 120.032,-112.6 h1.14
  text ".PCB_File_Name_No_Path" at 121.302,-115.648 h1.78
  text "Texas Instruments (TI) and/or its licensors do not warrant the accuracy or completeness of this specification" at -6.193,-119.759 h1.14
  text "ENGINEER:" at 120.032,-119.966 h1.14
  text "LAYOUT BY:" at 158.259,-119.966 h1.14
  text "or any information contained therein. TI and/or its licensors do not warrant that this design will meet" at -7.336,-122.621 h1.14
  text ".PRJ_Engineer" at 121.302,-123.903 h1.78
  text ".PCB_Layout" at 159.542,-123.903 h1.78
  text "the specifications, will be suitable for your application or fit for any particular purpose, or will operate in" at -7.336,-125.482 h1.14
  text ".Layer_Name" at -275.344,-125.958 h1.52
  text "ALTIUM DESIGNER VERSION:" at 158.259,-127.84 h1.14
  text "an implementation. TI and/or its licensors do not warrant that the design is production worthy. You should" at -7.336,-128.344 h1.14
  text "completely validate and test your design implementation to confirm the system functionality for your application." at -6.193,-131.206 h1.14
  text ".print_Scale" at 121.302,-131.227 h1.78
  text ".Application_BuildNumber" at 159.542,-131.227 h1.78
  text "1" at -263.118,-137.645 h1.78
  text "2" at -178.646,-137.645 h1.78
  text "3" at -94.064,-137.645 h1.78
  text "4" at -9.355,-137.645 h1.78
  text "5" at 75.1,-137.645 h1.78
  text "6" at 159.809,-137.645 h1.78
M10 Fab Notes:
  text ".Layer_Name" at -276.017,-104.177 h0.5
M11 Gerber Information:
  lines w0.254: -298.09,-105.997 -130.45,-105.997 ; -298.09,-100.832 -130.399,-100.832 ; -298.09,-95.668 -298.09,-111.162 -196.363,-111.162 -130.399,-111.162 -130.399,-95.668 -298.077,-95.668 -298.077,-111.162 -258.059,-111.162 ; -235.479,-111.162 -235.479,-95.668 ; -203.297,-100.832 -203.297,-95.668 ; -181.961,-100.832 -181.961,-95.668 ; -166.162,-111.327 -166.162,-106.175
  text "ALL ARTWORK VIEWED FROM TOP SIDE" at -296.477,-99.025 h0.5
  text "BOARD #:" at -233.574,-99.025 h0.5
  text ".PRJ_Number" at -219.718,-99.025 h0.5
  text "REV:" at -198.268,-99.025 h0.5
  text ".PCB_Rev" at -190.864,-99.025 h0.5
  text "SVN REV:" at -176.983,-99.025 h0.5
  text ".VersionControl_RevNumber" at -164.13,-99.025 h0.5
  text "LAYER NAME =" at -296.477,-104.177 h0.5
  text "TID #:" at -233.574,-104.189 h0.5
  text ".TID" at -219.718,-104.189 h0.5
  text "PLOT NAME =" at -296.477,-109.405 h0.5
  text ".plot_File_Name" at -276.017,-109.405 h0.5
  text "GENERATED    :" at -233.523,-109.405 h0.5
  text ".Print_Date" at -211.438,-109.405 h0.5
  text ".Print_Time" at -192.921,-109.405 h0.5
  text "TEXAS INSTRUMENTS" at -160.803,-109.405 h0.5
M12 Stackup:
  text ".Layer_Name" at -276.017,-104.177 h0.5
M13 Component Bodies Top:
  text ".Layer_Name" at -276.017,-104.177 h0.5
M14 Component Bodies Bottom:
  text ".Layer_Name" at -276.017,-104.177 h0.5
M15 Courtyards Top:
  text ".Layer_Name" at -276.017,-104.177 h0.5
M16 Courtyards Bottom:
  text ".Layer_Name" at -276.017,-104.177 h0.5
Drill Drawing:
  text ".Layer_Name" at -276.017,-104.177 h0.5
M17 Embedded Cavity:
  text ".Layer_Name" at -276.017,-104.177 h0.5
M18 Embedded Assembly:
  text ".Layer_Name" at -276.017,-104.177 h0.5
M19 Embedded Keepout:
  text ".Layer_Name" at -276.017,-104.177 h0.5

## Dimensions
-290.673,-92.531 to -265.273,-92.531 on M2 Board Dimensions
